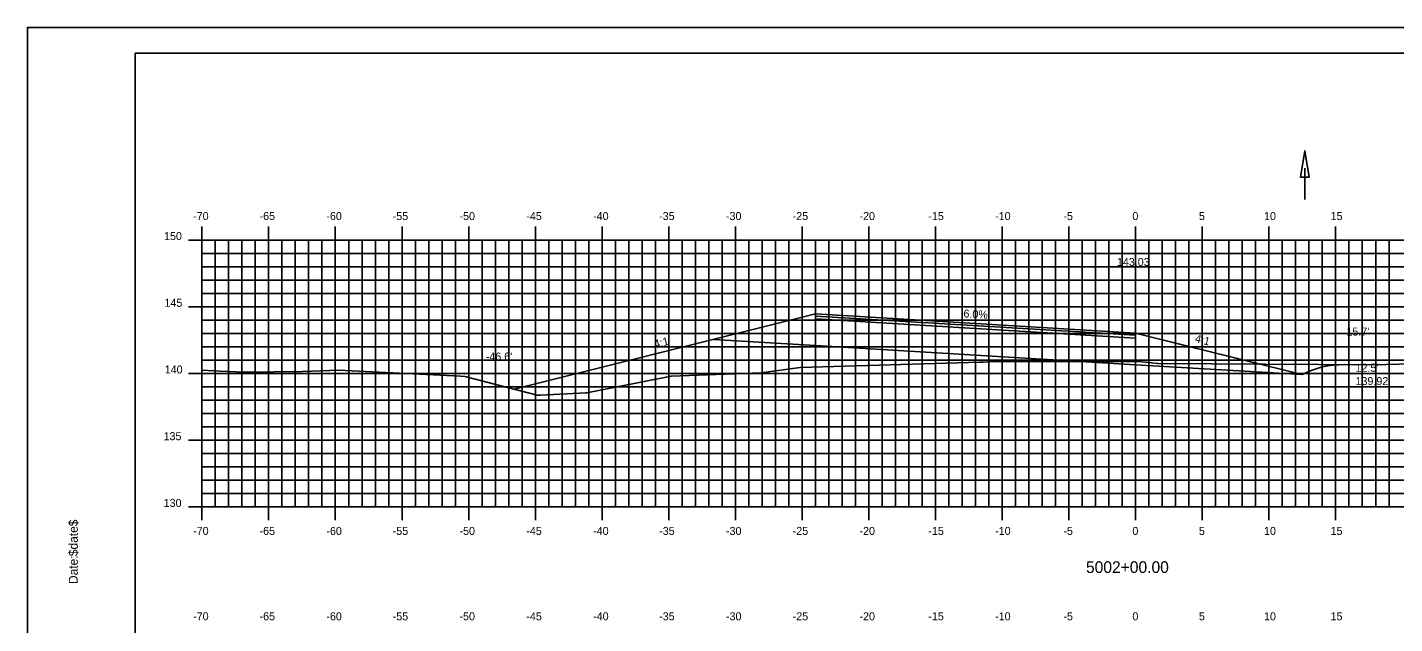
# Model space of a CAD drawing. Extents: x 851195 to 851367, y 365876 to 365986.
# Drawn here: x 851195 to 851297.6, y 365941.1 to 365985.8 of the extents above; entities that cross this region are included whole.
import ezdxf

# ---------------------------------------------------------------- set-up
doc = ezdxf.new("R2010")
doc.units = 0
for name, color, linetype in [('ANNOTATION', 7, 'Continuous'), ('BORDER', 7, 'Continuous'), ('D_Drainage_Ditch_Line', 7, 'Continuous'), ('D_Roadway_Centerline', 7, 'Continuous'), ('D_Roadway_Centerline_Text', 7, 'Continuous'), ('D_Roadway_Edge_TW', 7, 'Continuous'), ('D_Roadway_FinishedGrade', 7, 'Continuous'), ('D_Roadway_Pavement', 7, 'Continuous'), ('D_Roadway_SlopeLines', 7, 'Continuous'), ('D_Roadway_SubGrade', 7, 'Continuous'), ('D_Text_Standard', 7, 'Continuous'), ('H_V ANNOTATION', 7, 'Continuous'), ('MAJOR', 7, 'Continuous'), ('MINOR', 7, 'Continuous'), ('PLOT BOUNDARY', 7, 'Continuous'), ('S_Roadway_Centerline', 7, 'Continuous')]:
    doc.layers.add(name, color=color, linetype=linetype)

msp = doc.modelspace()

# ---------------------------------------------------------------- linework, layer by layer
at = {"layer": 'BORDER'}
msp.add_lwpolyline([(851203.14, 365878.83), (851363.14, 365878.83), (851363.14, 365983.83), (851203.14, 365983.83)], close=True, dxfattribs=at)
at = {"layer": 'D_Drainage_Ditch_Line'}
msp.add_line((851290.83, 365975.21), (851290.83, 365972.86), dxfattribs=at)
msp.add_lwpolyline([(851290.5, 365974.55), (851291.16, 365974.55), (851290.83, 365976.52)], close=True, dxfattribs=at)
at = {"layer": 'D_Roadway_Centerline'}
msp.add_lwpolyline([(851231.54, 365958.65), (851244.14, 365961.8), (851254.14, 365964.3), (851278.14, 365962.86), (851287.45, 365960.53)], dxfattribs=at)
at = {"layer": 'D_Roadway_Edge_TW'}
msp.add_lwpolyline([(851254.14, 365964.3), (851278.14, 365962.86), (851278.14, 365962.69), (851254.14, 365964.13)], close=True, dxfattribs=at)
at = {"layer": 'D_Roadway_FinishedGrade'}
for p, q in [((851254.14, 365961.93), (851246.51, 365962.39)), ((851278.14, 365960.49), (851290.6, 365959.75)), ((851290.6, 365959.75), (851290.62, 365959.76))]:
    msp.add_line(p, q, dxfattribs=at)
msp.add_arc((851293.75, 365953.5), 7, 89.6694, 116.5651, dxfattribs=at)
at = {"layer": 'D_Roadway_Pavement'}
msp.add_lwpolyline([(851254.14, 365964.13), (851278.14, 365962.69), (851278.14, 365962.49), (851254.14, 365963.93)], close=True, dxfattribs=at)
msp.add_lwpolyline([(851278.14, 365962.69), (851278.14, 365962.49)], dxfattribs=at)
msp.add_lwpolyline([(851278.14, 365962.69), (851278.14, 365962.49)], dxfattribs=at)
at = {"layer": 'D_Roadway_SlopeLines'}
for points in [[(851254.14, 365964.3), (851244.14, 365961.8), (851231.54, 365958.65)], [(851278.14, 365962.86), (851290.6, 365959.75)]]:
    msp.add_lwpolyline(points, dxfattribs=at)
at = {"layer": 'D_Roadway_SubGrade'}
for points in [[(851254.14, 365963.93), (851278.14, 365962.49)], [(851278.14, 365960.49), (851254.14, 365961.93)]]:
    msp.add_lwpolyline(points, dxfattribs=at)
at = {"layer": 'MAJOR'}
for p, q in [((851208.14, 365970.84), (851208.14, 365969.83)), ((851213.14, 365970.84), (851213.14, 365969.83)), ((851218.14, 365970.84), (851218.14, 365969.83)), ((851223.14, 365970.84), (851223.14, 365969.83)), ((851228.14, 365970.84), (851228.14, 365969.83)), ((851233.14, 365970.84), (851233.14, 365969.83)), ((851238.14, 365970.84), (851238.14, 365969.83)), ((851243.14, 365970.84), (851243.14, 365969.83)), ((851248.14, 365970.84), (851248.14, 365969.83)), ((851253.14, 365970.84), (851253.14, 365969.83)), ((851258.14, 365970.84), (851258.14, 365969.83)), ((851263.14, 365970.84), (851263.14, 365969.83)), ((851268.14, 365970.84), (851268.14, 365969.83)), ((851273.14, 365970.84), (851273.14, 365969.83)), ((851278.14, 365970.84), (851278.14, 365969.83)), ((851283.14, 365970.84), (851283.14, 365969.83)), ((851288.14, 365970.84), (851288.14, 365969.83)), ((851293.14, 365970.84), (851293.14, 365969.83)), ((851207.14, 365969.83), (851208.14, 365969.83)), ((851208.14, 365969.83), (851348.14, 365969.83)), ((851208.14, 365949.83), (851208.14, 365969.83)), ((851208.14, 365949.83), (851208.14, 365969.83)), ((851208.14, 365969.83), (851348.14, 365969.83)), ((851213.14, 365949.83), (851213.14, 365969.83)), ((851218.14, 365949.83), (851218.14, 365969.83)), ((851223.14, 365949.83), (851223.14, 365969.83)), ((851228.14, 365949.83), (851228.14, 365969.83)), ((851233.14, 365949.83), (851233.14, 365969.83)), ((851238.14, 365949.83), (851238.14, 365969.83)), ((851243.14, 365949.83), (851243.14, 365969.83)), ((851248.14, 365949.83), (851248.14, 365969.83)), ((851253.14, 365949.83), (851253.14, 365969.83)), ((851258.14, 365949.83), (851258.14, 365969.83)), ((851263.14, 365949.83), (851263.14, 365969.83)), ((851268.14, 365949.83), (851268.14, 365969.83)), ((851273.14, 365949.83), (851273.14, 365969.83)), ((851278.14, 365949.83), (851278.14, 365969.83)), ((851283.14, 365949.83), (851283.14, 365969.83)), ((851288.14, 365949.83), (851288.14, 365969.83)), ((851293.14, 365949.83), (851293.14, 365969.83)), ((851207.14, 365964.83), (851208.14, 365964.83)), ((851208.14, 365964.83), (851348.14, 365964.83)), ((851207.14, 365959.83), (851208.14, 365959.83)), ((851208.14, 365959.83), (851348.14, 365959.83)), ((851207.14, 365954.83), (851208.14, 365954.83)), ((851208.14, 365954.83), (851348.14, 365954.83)), ((851207.14, 365949.83), (851208.14, 365949.83)), ((851208.14, 365949.83), (851348.14, 365949.83)), ((851208.14, 365949.83), (851348.14, 365949.83)), ((851208.14, 365948.83), (851208.14, 365949.83)), ((851213.14, 365948.83), (851213.14, 365949.83)), ((851218.14, 365948.83), (851218.14, 365949.83)), ((851223.14, 365948.83), (851223.14, 365949.83)), ((851228.14, 365948.83), (851228.14, 365949.83)), ((851233.14, 365948.83), (851233.14, 365949.83)), ((851238.14, 365948.83), (851238.14, 365949.83)), ((851243.14, 365948.83), (851243.14, 365949.83)), ((851248.14, 365948.83), (851248.14, 365949.83)), ((851253.14, 365948.83), (851253.14, 365949.83)), ((851258.14, 365948.83), (851258.14, 365949.83)), ((851263.14, 365948.83), (851263.14, 365949.83)), ((851268.14, 365948.83), (851268.14, 365949.83)), ((851273.14, 365948.83), (851273.14, 365949.83)), ((851278.14, 365948.83), (851278.14, 365949.83)), ((851283.14, 365948.83), (851283.14, 365949.83)), ((851288.14, 365948.83), (851288.14, 365949.83)), ((851293.14, 365948.83), (851293.14, 365949.83))]:
    msp.add_line(p, q, dxfattribs=at)
at = {"layer": 'MINOR'}
for p, q in [((851208.14, 365968.83), (851348.14, 365968.83)), ((851208.14, 365968.83), (851209.14, 365968.83)), ((851209.14, 365949.83), (851209.14, 365969.83)), ((851210.14, 365949.83), (851210.14, 365969.83)), ((851211.14, 365949.83), (851211.14, 365969.83)), ((851212.14, 365949.83), (851212.14, 365969.83)), ((851214.14, 365949.83), (851214.14, 365969.83)), ((851215.14, 365949.83), (851215.14, 365969.83)), ((851216.14, 365949.83), (851216.14, 365969.83)), ((851217.14, 365949.83), (851217.14, 365969.83)), ((851219.14, 365949.83), (851219.14, 365969.83)), ((851220.14, 365949.83), (851220.14, 365969.83)), ((851221.14, 365949.83), (851221.14, 365969.83)), ((851222.14, 365949.83), (851222.14, 365969.83)), ((851224.14, 365949.83), (851224.14, 365969.83)), ((851225.14, 365949.83), (851225.14, 365969.83)), ((851226.14, 365949.83), (851226.14, 365969.83)), ((851227.14, 365949.83), (851227.14, 365969.83)), ((851229.14, 365949.83), (851229.14, 365969.83)), ((851230.14, 365949.83), (851230.14, 365969.83)), ((851231.14, 365949.83), (851231.14, 365969.83)), ((851232.14, 365949.83), (851232.14, 365969.83)), ((851234.14, 365949.83), (851234.14, 365969.83)), ((851235.14, 365949.83), (851235.14, 365969.83)), ((851236.14, 365949.83), (851236.14, 365969.83)), ((851237.14, 365949.83), (851237.14, 365969.83)), ((851239.14, 365949.83), (851239.14, 365969.83)), ((851240.14, 365949.83), (851240.14, 365969.83)), ((851241.14, 365949.83), (851241.14, 365969.83)), ((851242.14, 365949.83), (851242.14, 365969.83)), ((851244.14, 365949.83), (851244.14, 365969.83)), ((851245.14, 365949.83), (851245.14, 365969.83)), ((851246.14, 365949.83), (851246.14, 365969.83)), ((851247.14, 365949.83), (851247.14, 365969.83)), ((851249.14, 365949.83), (851249.14, 365969.83)), ((851250.14, 365949.83), (851250.14, 365969.83)), ((851251.14, 365949.83), (851251.14, 365969.83)), ((851252.14, 365949.83), (851252.14, 365969.83)), ((851254.14, 365949.83), (851254.14, 365969.83)), ((851255.14, 365949.83), (851255.14, 365969.83)), ((851256.14, 365949.83), (851256.14, 365969.83)), ((851257.14, 365949.83), (851257.14, 365969.83)), ((851259.14, 365949.83), (851259.14, 365969.83)), ((851260.14, 365949.83), (851260.14, 365969.83)), ((851261.14, 365949.83), (851261.14, 365969.83)), ((851262.14, 365949.83), (851262.14, 365969.83)), ((851264.14, 365949.83), (851264.14, 365969.83)), ((851265.14, 365949.83), (851265.14, 365969.83)), ((851266.14, 365949.83), (851266.14, 365969.83)), ((851267.14, 365949.83), (851267.14, 365969.83)), ((851269.14, 365949.83), (851269.14, 365969.83)), ((851270.14, 365949.83), (851270.14, 365969.83)), ((851271.14, 365949.83), (851271.14, 365969.83)), ((851272.14, 365949.83), (851272.14, 365969.83)), ((851274.14, 365949.83), (851274.14, 365969.83)), ((851275.14, 365949.83), (851275.14, 365969.83)), ((851276.14, 365949.83), (851276.14, 365969.83)), ((851277.14, 365949.83), (851277.14, 365969.83)), ((851279.14, 365949.83), (851279.14, 365969.83)), ((851280.14, 365949.83), (851280.14, 365969.83)), ((851281.14, 365949.83), (851281.14, 365969.83)), ((851282.14, 365949.83), (851282.14, 365969.83)), ((851284.14, 365949.83), (851284.14, 365969.83)), ((851285.14, 365949.83), (851285.14, 365969.83)), ((851286.14, 365949.83), (851286.14, 365969.83)), ((851287.14, 365949.83), (851287.14, 365969.83)), ((851289.14, 365949.83), (851289.14, 365969.83)), ((851290.14, 365949.83), (851290.14, 365969.83)), ((851291.14, 365949.83), (851291.14, 365969.83)), ((851292.14, 365949.83), (851292.14, 365969.83)), ((851294.14, 365949.83), (851294.14, 365969.83)), ((851295.14, 365949.83), (851295.14, 365969.83)), ((851296.14, 365949.83), (851296.14, 365969.83)), ((851297.14, 365949.83), (851297.14, 365969.83)), ((851208.14, 365967.83), (851348.14, 365967.83)), ((851208.14, 365967.83), (851209.14, 365967.83)), ((851208.14, 365966.83), (851348.14, 365966.83)), ((851208.14, 365966.83), (851209.14, 365966.83)), ((851208.14, 365965.83), (851348.14, 365965.83)), ((851208.14, 365965.83), (851209.14, 365965.83)), ((851208.14, 365963.83), (851348.14, 365963.83)), ((851208.14, 365963.83), (851209.14, 365963.83)), ((851208.14, 365962.83), (851348.14, 365962.83)), ((851208.14, 365962.83), (851209.14, 365962.83)), ((851208.14, 365961.83), (851348.14, 365961.83)), ((851208.14, 365961.83), (851209.14, 365961.83)), ((851208.14, 365960.83), (851348.14, 365960.83)), ((851208.14, 365960.83), (851209.14, 365960.83)), ((851208.14, 365958.83), (851348.14, 365958.83)), ((851208.14, 365958.83), (851209.14, 365958.83)), ((851208.14, 365957.83), (851348.14, 365957.83)), ((851208.14, 365957.83), (851209.14, 365957.83)), ((851208.14, 365956.83), (851348.14, 365956.83)), ((851208.14, 365956.83), (851209.14, 365956.83)), ((851208.14, 365955.83), (851348.14, 365955.83)), ((851208.14, 365955.83), (851209.14, 365955.83)), ((851208.14, 365953.83), (851348.14, 365953.83)), ((851208.14, 365953.83), (851209.14, 365953.83)), ((851208.14, 365952.83), (851348.14, 365952.83)), ((851208.14, 365952.83), (851209.14, 365952.83)), ((851208.14, 365951.83), (851348.14, 365951.83)), ((851208.14, 365951.83), (851209.14, 365951.83)), ((851208.14, 365950.83), (851348.14, 365950.83)), ((851208.14, 365950.83), (851209.14, 365950.83))]:
    msp.add_line(p, q, dxfattribs=at)
at = {"layer": 'PLOT BOUNDARY'}
msp.add_lwpolyline([(851195.05, 365875.77), (851365.05, 365875.77), (851365.05, 365985.77), (851195.05, 365985.77)], close=True, dxfattribs=at)
at = {"layer": 'S_Roadway_Centerline'}
msp.add_lwpolyline([(851208.14, 365960.07), (851209.49, 365960.01), (851211.32, 365959.93), (851215.69, 365959.99), (851218.37, 365960.09), (851227.52, 365959.62), (851227.84, 365959.6), (851227.95, 365959.57), (851233.28, 365958.2), (851233.53, 365958.21), (851236.92, 365958.38), (851236.96, 365958.38), (851237, 365958.38), (851243.33, 365959.64), (851250.07, 365959.89), (851253, 365960.27), (851266.46, 365960.68), (851266.72, 365960.67), (851267.11, 365960.7), (851278.38, 365960.74), (851279.82, 365960.58), (851295.9, 365960.48), (851301.91, 365960.62)], dxfattribs=at)

# ---------------------------------------------------------------- texts
at = {"layer": 'ANNOTATION'}
for s, rotation, p in [('6.0%', 356.5664, (851265.22, 365964.04)), ('4:1', 345.9638, (851282.55, 365962.19)), ('4:1', 14.0362, (851242.11, 365961.72))]:
    msp.add_text(s, height=0.6, rotation=rotation, dxfattribs=at).set_placement(p)
at = {"layer": 'BORDER'}
for s, p in [('$date$', (851198.83, 365946.14)), ('Date:', (851198.83, 365944.05))]:
    msp.add_text(s, height=0.67, rotation=90, dxfattribs=at).set_placement(p)
at = {"layer": 'D_Roadway_Centerline_Text'}
msp.add_text('143.03', height=0.6, dxfattribs=at).set_placement((851276.74, 365967.89))
at = {"layer": 'D_Text_Standard'}
for s, p in [("15.7'", (851293.95, 365962.67)), ("-46.6'", (851229.42, 365960.8)), ("12.5' ", (851294.63, 365959.96)), ('139.92', (851294.63, 365958.96))]:
    msp.add_text(s, height=0.6, dxfattribs=at).set_placement(p)
at = {"layer": 'H_V ANNOTATION'}
for s, height, p in [('-70', 0.6, (851207.48, 365971.33)), ('-65', 0.6, (851212.46, 365971.33)), ('-60', 0.6, (851217.47, 365971.33)), ('-55', 0.6, (851222.44, 365971.33)), ('-50', 0.6, (851227.45, 365971.33)), ('-45', 0.6, (851232.46, 365971.33)), ('-40', 0.6, (851237.47, 365971.33)), ('-35', 0.6, (851242.42, 365971.33)), ('-30', 0.6, (851247.43, 365971.33)), ('-25', 0.6, (851252.43, 365971.33)), ('-20', 0.6, (851257.44, 365971.33)), ('-15', 0.6, (851262.6, 365971.33)), ('-10', 0.6, (851267.61, 365971.33)), ('-5', 0.6, (851272.73, 365971.33)), ('0', 0.6, (851277.9, 365971.33)), ('5', 0.6, (851282.89, 365971.33)), ('10', 0.6, (851287.77, 365971.33)), ('15', 0.6, (851292.76, 365971.33)), ('150', 0.6, (851205.3, 365969.83)), ('145', 0.6, (851205.33, 365964.83)), ('140', 0.6, (851205.35, 365959.83)), ('135', 0.6, (851205.26, 365954.83)), ('130', 0.6, (851205.27, 365949.83)), ('-70', 0.6, (851207.48, 365947.73)), ('-65', 0.6, (851212.46, 365947.73)), ('-60', 0.6, (851217.47, 365947.73)), ('-55', 0.6, (851222.44, 365947.73)), ('-50', 0.6, (851227.45, 365947.73)), ('-45', 0.6, (851232.46, 365947.73)), ('-40', 0.6, (851237.47, 365947.73)), ('-35', 0.6, (851242.42, 365947.73)), ('-30', 0.6, (851247.43, 365947.73)), ('-25', 0.6, (851252.43, 365947.73)), ('-20', 0.6, (851257.44, 365947.73)), ('-15', 0.6, (851262.6, 365947.73)), ('-10', 0.6, (851267.61, 365947.73)), ('-5', 0.6, (851272.73, 365947.73)), ('0', 0.6, (851277.9, 365947.73)), ('5', 0.6, (851282.89, 365947.73)), ('10', 0.6, (851287.77, 365947.73)), ('15', 0.6, (851292.76, 365947.73)), ('5002+00.00', 0.875, (851274.42, 365944.88)), ('-70', 0.6, (851207.48, 365941.33)), ('-65', 0.6, (851212.46, 365941.33)), ('-60', 0.6, (851217.47, 365941.33)), ('-55', 0.6, (851222.44, 365941.33)), ('-50', 0.6, (851227.45, 365941.33)), ('-45', 0.6, (851232.46, 365941.33)), ('-40', 0.6, (851237.47, 365941.33)), ('-35', 0.6, (851242.42, 365941.33)), ('-30', 0.6, (851247.43, 365941.33)), ('-25', 0.6, (851252.43, 365941.33)), ('-20', 0.6, (851257.44, 365941.33)), ('-15', 0.6, (851262.6, 365941.33)), ('-10', 0.6, (851267.61, 365941.33)), ('-5', 0.6, (851272.73, 365941.33)), ('0', 0.6, (851277.9, 365941.33)), ('5', 0.6, (851282.89, 365941.33)), ('10', 0.6, (851287.77, 365941.33)), ('15', 0.6, (851292.76, 365941.33))]:
    msp.add_text(s, height=height, dxfattribs=at).set_placement(p)
at = {"layer": 'MAJOR'}
msp.add_text('-', height=0.006, dxfattribs=at).set_placement((851208.14, 365949.83))

doc.saveas('drawing.dxf')
